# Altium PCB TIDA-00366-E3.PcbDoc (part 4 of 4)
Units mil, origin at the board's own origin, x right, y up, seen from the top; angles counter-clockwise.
Board outline 6298.95 x 6141.73 mil, 4 copper layers (Top Layer, GND, PWR, Bottom Layer), stack 79.834 mil thick; 362 components, 168 nets, 919 pads, 271 vias.
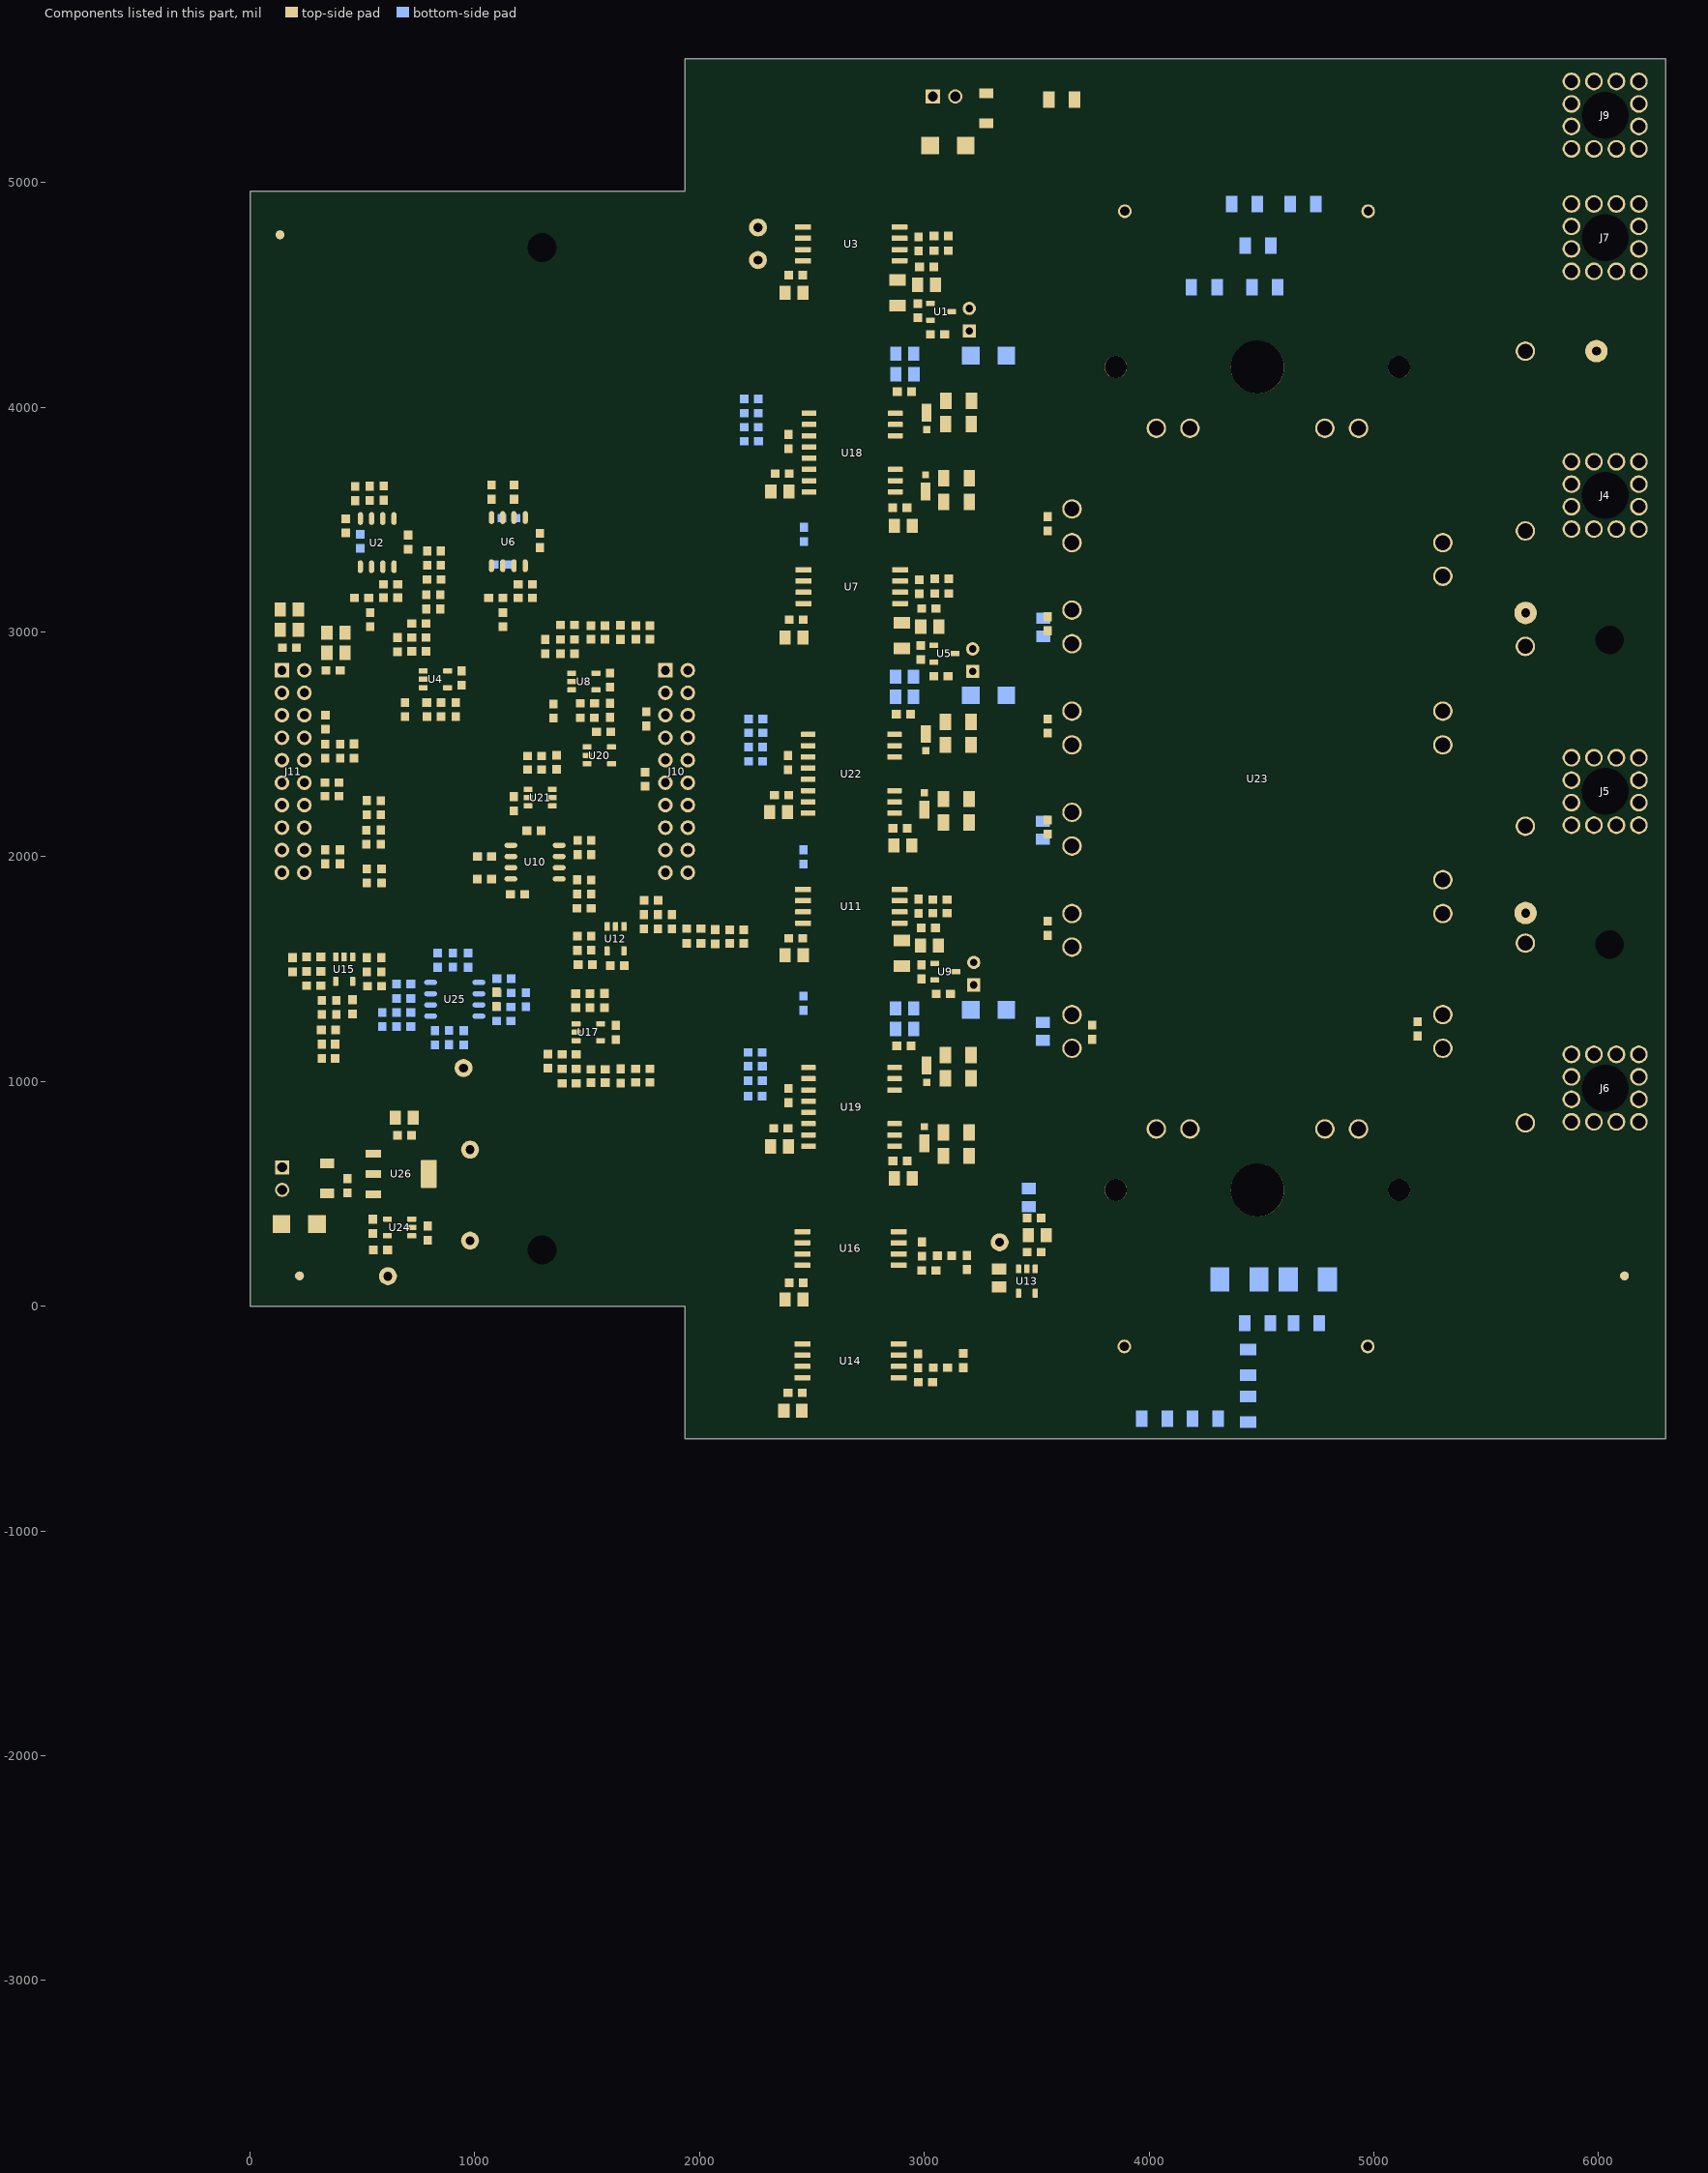
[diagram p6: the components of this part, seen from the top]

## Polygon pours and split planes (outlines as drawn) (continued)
U_TOP_REF on Bottom Layer "Top Layer-No Net 1" (solid, remove dead copper, pour order 81): 5754.73,4304.45 5768.22,4290.96 5768.22,4259.45 5768.22,4202.94 5754.73,4189.45 5564.73,4189.45 5479.73,4104.45 5371.5,3996.21 5371.5,3594.45 5371.5,3201.21 5359.73,3189.45 5254.73,3189.45 5249.73,3194.45 5249.73,4029.45 5519.73,4299.45 5524.73,4304.45 5754.73,4304.45
VDC+ on Bottom Layer "Top Layer-No Net 1" (solid, remove dead copper, pour order 86): 5884.73,4949.45 4719.73,4949.45 4709.73,4939.45 4709.73,-210.55 4749.73,-250.55 5024.73,-250.55 5044.73,-230.55 5044.73,-105.55 4994.73,-55.55 4994.73,4499.45 5054.73,4559.45 5924.73,4559.45 6229.73,4559.45 6244.73,4574.45 6244.73,4934.45 6229.73,4949.45
VDC- on Bottom Layer "Top Layer-No Net 1" (solid, remove dead copper, pour order 92): 6244.73,5474.45 6244.73,5124.45 6224.73,5104.45 4269.73,5104.45 4224.73,5059.45 4224.73,-225.55 4199.73,-250.55 3829.73,-250.55 3814.73,-235.55 3814.73,-125.55 3934.73,-5.55 3934.73,4484.45 3764.73,4654.45 3764.73,5464.45 3789.73,5489.45 3794.73,5494.45 3869.73,5494.45 6224.73,5494.45 6244.73,5474.45
VCC_U on PWR "PWR-No Net" (solid, remove dead copper, pour order 129): 3246.73,4194.45 3246.73,3865.45 3239.73,3858.45 2825.73,3858.45 2821.73,3862.45 2820.73,3863.45 2820.73,3875.45 2820.73,4830.45 2839.73,4849.45 3226.73,4849.45 3242.73,4833.45 3246.73,4829.45 3246.73,4196.45
VCC_V on PWR "PWR-No Net" (solid, remove dead copper, pour order 131): 3246.73,2765.45 3246.73,2431.45 3241.73,2426.45 3238.73,2429.45 2862.73,2429.45 2827.32,2429.45 2819.73,2437.04 2819.73,3311.5 2830.69,3322.45 3224.73,3322.45 3237.73,3309.45 3246.73,3300.45 3246.73,2766.45
VCC_W on PWR "PWR-No Net" (solid, remove dead copper, pour order 133): 3247.73,1282.45 3247.73,953.45 3241.73,947.45 2823.86,947.45 2819.86,951.45 2819.86,1892.1 2824.34,1896.58 3225.61,1896.58 3242.73,1879.45 3247.73,1874.45 3247.73,1289.45
+16V_GPS on PWR "PWR-No Net" (solid, remove dead copper, pour order 134): 3324.73,4266.45 3324.73,3745.45 3313.73,3734.45 2825.65,3734.45 2820.73,3729.54 2820.73,3443.45 2831.73,3432.45 3284.73,3432.45 3322.73,3394.45 3324.73,3392.45 3324.73,2759.45 3324.73,2319.45 3313.73,2308.45 2826.65,2308.45 2819.73,2301.54 2819.73,2020.45 2830.73,2009.45 3300.73,2009.45 3316.73,1993.45 3324.73,1985.45 3324.73,1278.45 3324.73,868.45 3289.73,833.45 3282.73,826.45 2855.73,826.45 2823.86,826.45 2819.86,822.45 2819.86,540.86 2831.86,528.86 3547.15,528.86 3561.15,528.86 3575.73,543.45 3575.73,5488.45 3569.73,5494.45 3334.73,5494.45 3324.73,5484.45
W_PHASE on PWR "Top Layer-No Net 1" (solid, remove dead copper, pour order 100): 6214.73,1179.45 5797.73,1179.45 5787.73,1169.45 5787.73,879.45 5779.73,871.45 5595.73,871.45 5579.25,854.96 5579.25,769.94 5592.73,756.45 6211.73,756.45 6234.73,779.45 6234.73,1160.45 6214.73,1180.45
W_TOP_REF on PWR "Top Layer-No Net 1" (solid, remove dead copper, pour order 71): 5239.73,1944.45 5239.73,1714.45 5259.73,1694.45 5569.73,1694.45 5579.73,1684.45 5579.73,1584.45 5589.73,1574.45 5753.22,1574.45 5768.22,1589.45 5768.22,1740.96 5749.73,1759.45 5724.73,1784.45 5384.73,1784.45 5371.5,1797.69 5371.5,1799.45 5371.5,1937.69 5359.73,1949.45 5244.73,1949.45 5239.73,1944.45
V_PHASE on PWR "Top Layer-No Net 1" (solid, remove dead copper, pour order 91): 6214.73,2499.45 5797.73,2499.45 5787.73,2489.45 5787.73,2199.45 5779.73,2191.45 5595.73,2191.45 5579.25,2174.96 5579.25,2089.94 5592.73,2076.45 6211.73,2076.45 6234.73,2099.45 6234.73,2480.45 6214.73,2500.45
V_TOP_REF on PWR "Top Layer-No Net 1" (solid, remove dead copper, pour order 76): 5254.73,2689.45 5254.73,2459.45 5264.73,2449.45 5361.5,2449.45 5371.5,2459.45 5371.5,2866.21 5389.73,2884.45 5759.73,2884.45 5764.73,2889.45 5764.73,2984.45 5749.73,2999.45 5269.73,2999.45 5254.73,2984.45
U_PHASE on PWR "Top Layer-No Net 1" (solid, remove dead copper, pour order 96): 6214.73,3811.45 5797.73,3811.45 5787.73,3801.45 5787.73,3511.45 5779.73,3503.45 5595.73,3503.45 5579.25,3486.96 5579.25,3401.94 5592.73,3388.45 6211.73,3388.45 6234.73,3411.45 6234.73,3792.45 6214.73,3812.45
U_TOP_REF on PWR "Top Layer-No Net 1" (solid, remove dead copper, pour order 80): 5754.73,4304.45 5768.22,4290.96 5768.22,4259.45 5768.22,4202.94 5754.73,4189.45 5564.73,4189.45 5479.73,4104.45 5371.5,3996.21 5371.5,3594.45 5371.5,3201.21 5359.73,3189.45 5254.73,3189.45 5249.73,3194.45 5249.73,4029.45 5519.73,4299.45 5524.73,4304.45 5754.73,4304.45
VDC+ on PWR "Top Layer-No Net 1" (solid, remove dead copper, pour order 85): 5884.73,4949.45 4719.73,4949.45 4709.73,4939.45 4709.73,-210.55 4749.73,-250.55 5024.73,-250.55 5044.73,-230.55 5044.73,-105.55 4994.73,-55.55 4994.73,4499.45 5054.73,4559.45 5924.73,4559.45 6229.73,4559.45 6244.73,4574.45 6244.73,4934.45 6229.73,4949.45
VDC- on PWR "Top Layer-No Net 1" (solid, remove dead copper, pour order 90): 6244.73,5474.45 6244.73,5124.45 6224.73,5104.45 4269.73,5104.45 4224.73,5059.45 4224.73,-225.55 4199.73,-250.55 3829.73,-250.55 3814.73,-235.55 3814.73,-125.55 3934.73,-5.55 3934.73,4484.45 3764.73,4654.45 3764.73,5464.45 3789.73,5489.45 3794.73,5494.45 3869.73,5494.45 6224.73,5494.45 6244.73,5474.45
5V_VDC on PWR "Top Layer-No Net 1" (solid, remove dead copper, pour order 106): 2824.73,424.45 2824.73,-530.55 2844.73,-550.55 3544.73,-550.55 3559.73,-535.55 3559.73,404.45 3539.73,424.45 3527.47,436.72 2837,436.72
VCCI on PWR "Top Layer-No Net 1" (solid, remove dead copper, pour order 126): 2480,5495 1990,5495 1980,5485 1980,4945 1950,4915 45,4915 30,4900 30,55 45,40 1960,40 1980,20 1980,-540 1990,-550 2515,-550 2520,-545 2520,5490 2515,5495
GND1 on GND "Top Layer-No Net 1" (solid, remove dead copper, pour order 136): 3324.73,5484.45 3324.73,533.45 3329.73,528.45 3560.73,528.45 3575.73,543.45 3575.73,5488.45 3569.73,5494.45 3334.73,5494.45
W_TOP_REF on GND "PWR-No Net" (solid, remove dead copper, pour order 132): 3247.73,1282.45 3247.73,953.45 3241.73,947.45 2823.86,947.45 2819.86,951.45 2819.86,1892.1 2824.34,1896.58 3225.61,1896.58 3242.73,1879.45 3247.73,1874.45 3247.73,1289.45
V_TOP_REF on GND "PWR-No Net" (solid, remove dead copper, pour order 130): 3246.73,2765.45 3246.73,2431.45 3241.73,2426.45 3238.73,2429.45 2862.73,2429.45 2827.32,2429.45 2819.73,2437.04 2819.73,3311.5 2830.69,3322.45 3224.73,3322.45 3237.73,3309.45 3246.73,3300.45 3246.73,2766.45
U_TOP_REF on GND "PWR-No Net" (solid, remove dead copper, pour order 128): 3246.73,4194.45 3246.73,3865.45 3239.73,3858.45 2825.73,3858.45 2821.73,3862.45 2820.73,3863.45 2820.73,3875.45 2820.73,4830.45 2839.73,4849.45 3226.73,4849.45 3242.73,4833.45 3246.73,4829.45 3246.73,4196.45
VDC- on GND "Top Layer-No Net 1" (solid, remove dead copper, pour order 105): 2824.73,424.45 2824.73,-530.55 2844.73,-550.55 3544.73,-550.55 3559.73,-535.55 3559.73,404.45 3539.73,424.45 3527.47,436.72 2837,436.72
W_PHASE on GND "Top Layer-No Net 1" (solid, remove dead copper, pour order 99): 6214.73,1179.45 5797.73,1179.45 5787.73,1169.45 5787.73,879.45 5779.73,871.45 5595.73,871.45 5579.25,854.96 5579.25,769.94 5592.73,756.45 6211.73,756.45 6234.73,779.45 6234.73,1160.45 6214.73,1180.45
W_TOP_REF on GND "Top Layer-No Net 1" (solid, remove dead copper, pour order 70): 5239.73,1944.45 5239.73,1714.45 5259.73,1694.45 5569.73,1694.45 5579.73,1684.45 5579.73,1584.45 5589.73,1574.45 5753.22,1574.45 5768.22,1589.45 5768.22,1740.96 5749.73,1759.45 5724.73,1784.45 5384.73,1784.45 5371.5,1797.69 5371.5,1799.45 5371.5,1937.69 5359.73,1949.45 5244.73,1949.45 5239.73,1944.45
V_PHASE on GND "Top Layer-No Net 1" (solid, remove dead copper, pour order 89): 6214.73,2499.45 5797.73,2499.45 5787.73,2489.45 5787.73,2199.45 5779.73,2191.45 5595.73,2191.45 5579.25,2174.96 5579.25,2089.94 5592.73,2076.45 6211.73,2076.45 6234.73,2099.45 6234.73,2480.45 6214.73,2500.45
V_TOP_REF on GND "Top Layer-No Net 1" (solid, remove dead copper, pour order 75): 5254.73,2689.45 5254.73,2459.45 5264.73,2449.45 5361.5,2449.45 5371.5,2459.45 5371.5,2866.21 5389.73,2884.45 5759.73,2884.45 5764.73,2889.45 5764.73,2984.45 5749.73,2999.45 5269.73,2999.45 5254.73,2984.45
U_PHASE on GND "Top Layer-No Net 1" (solid, remove dead copper, pour order 95): 6214.73,3811.45 5797.73,3811.45 5787.73,3801.45 5787.73,3511.45 5779.73,3503.45 5595.73,3503.45 5579.25,3486.96 5579.25,3401.94 5592.73,3388.45 6211.73,3388.45 6234.73,3411.45 6234.73,3792.45 6214.73,3812.45
U_TOP_REF on GND "Top Layer-No Net 1" (solid, remove dead copper, pour order 79): 5754.73,4304.45 5768.22,4290.96 5768.22,4259.45 5768.22,4202.94 5754.73,4189.45 5564.73,4189.45 5479.73,4104.45 5371.5,3996.21 5371.5,3594.45 5371.5,3201.21 5359.73,3189.45 5254.73,3189.45 5249.73,3194.45 5249.73,4029.45 5519.73,4299.45 5524.73,4304.45 5754.73,4304.45
VDC+ on GND "Top Layer-No Net 1" (solid, remove dead copper, pour order 84): 5884.73,4949.45 4719.73,4949.45 4709.73,4939.45 4709.73,-210.55 4749.73,-250.55 5024.73,-250.55 5044.73,-230.55 5044.73,-105.55 4994.73,-55.55 4994.73,4499.45 5054.73,4559.45 5924.73,4559.45 6229.73,4559.45 6244.73,4574.45 6244.73,4934.45 6229.73,4949.45
VDC- on GND "Top Layer-No Net 1" (solid, remove dead copper, pour order 88): 6244.73,5474.45 6244.73,5124.45 6224.73,5104.45 4269.73,5104.45 4224.73,5059.45 4224.73,-225.55 4199.73,-250.55 3829.73,-250.55 3814.73,-235.55 3814.73,-125.55 3934.73,-5.55 3934.73,4484.45 3764.73,4654.45 3764.73,5464.45 3789.73,5489.45 3794.73,5494.45 3869.73,5494.45 6224.73,5494.45 6244.73,5474.45
GND on GND "Top Layer-No Net 1" (solid, remove dead copper, pour order 125): 2480,5495 1990,5495 1980,5485 1980,4945 1950,4915 45,4915 30,4900 30,55 45,40 1960,40 1980,20 1980,-540 1990,-550 2515,-550 2520,-545 2520,5490 2515,5495

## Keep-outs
Keep-Out Layer:
  text ".Layer_Name" at 111.73,-3325.04 h60

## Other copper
Top Layer:
  text ".layer_Name" at 126.73,-3314.55 h60
GND:
  text "GND" at 194.73,-3310.55 h60
PWR:
  text "PWR" at 204.73,-3310.55 h60
Bottom Layer:
  text ".Layer_Name" at 185.73,-3324.55 h60
Multi-Layer:
  pour cut-out: 2817.3,-545 2522.7,-545 2522.7,5500 2817.3,5500

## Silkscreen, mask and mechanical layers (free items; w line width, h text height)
Top Overlay:
  circle w10: c5989.73,4249.45 r70.51
  circle w10: c5674.73,3084.45 r70.51
  circle w10: c5674.73,1749.45 r70.51
  lines w6: 257.73,1311.4 281.73,1311.4 ; 276.73,1593.4 276.73,1638.4 ; 449.73,1629.45 454.73,1624.45 454.73,1594.45 ; 455.73,2867.45 463.73,2859.45 474.73,2859.45 ; 544.73,2479.45 504.73,2479.45 ; 545.93,2278.43 545.93,2290.64 553.74,2298.45 ; 550.73,803.45 567.73,803.45 583.53,787.65 626.75,787.65 ; 614.73,3074.45 624.73,3084.45 624.73,3109.45 ; 729,2726.02 729,2713 746,2696 ; 814.73,2549.45 814.73,2589.45 ; 1238.06,2935.12 1276.06,2935.12 ; 1354.73,2873.27 1354.73,2864.45 1474.06,2864.45 1474.06,2872.62 ; 1354.73,3069.45 1354.73,3094.45 1394.73,3134.45 1394.73,3249.45 1504.73,3249.45 1504.73,3119.45 1479.73,3094.45 1479.73,3069.45 ; 1379.73,1189.45 1419.73,1189.45 ; 1419.73,1609.45 1389.73,1609.45 ; 1424.73,3069.45 1424.73,3099.45 ; 1429.73,914.45 1429.73,944.45 ; 1483.5,1926.93 1483.5,1939.45 1492.96,1948.91 ; 1639.73,2784.45 1664.73,2784.45 ; 1659.73,1219.45 1689.73,1219.45 ; 2950.73,125.45 2953.02,125.45 2959.75,132.18 ; 2955.73,333.45 2955.73,321.17 2962.47,314.43 ; 3069.72,4597.18 3119.47,4597.18 3127.73,4605.45 ; 3077.72,1656.18 3120.47,1656.18 3134.73,1670.45 ; 3079.72,3077.18 3130.47,3077.18 3136.73,3083.45 ; 3102.29,4483.5 3133.79,4515 3140,4515 ; 3116.29,2962.5 3124.5,2962.5 3152,2990 ; 3120.29,1547.5 3137.5,1547.5 3150,1560 3150,1595 3154,1599 3160,1605 ; 3131.72,-300.82 3131.72,-312.53 ; 3139.73,179.45 3149.72,189.43 3149.72,197.18 ; 276.73,1638.4 284.73,1630.4 268.73,1630.4 276.73,1638.4 ; 281.73,1311.4 274.73,1318.4 274.73,1301.4 281.73,1308.4 281.73,1311.4 ; 504.73,2479.45 514.73,2469.45 514.73,2489.45 504.73,2479.45 ; 814.73,2589.45 824.73,2579.45 804.73,2579.45 814.73,2589.45 ; 1389.73,1609.45 1399.73,1599.45 1399.73,1619.45 1389.73,1609.45 ; 1424.73,3099.45 1434.73,3089.45 1414.73,3089.45 1424.73,3099.45 ; 1429.73,944.45 1439.73,934.45 1419.73,934.45 1429.73,944.45 ; 3131.72,-312.53 3131.73,-312.55
  lines w10: -757.27,-3396.72 5842.73,-3396.72 ; -757.27,-3193.38 5844.73,-3193.38 ; -757.27,-2990.05 -757.27,-3600.05 3247.73,-3600.05 5844.73,-3600.05 ; -756.77,-3600.05 -756.77,-2990.05 5844.73,-2990.05 ; 1725.73,-3598.55 1725.73,-2988.55 ; 3934.73,-3194.88 3934.73,-2991.55 ; 4608.73,-3600.38 4608.73,-3397.55 ; 5844.23,-3600.05 5844.23,-2990.05
  text "GD_Supply" at 2530,5460 h50
  text "GND" at 3225,5460 h50
  text "VDC-" at 5780,5235 h50 r90
  text "840V DC" at 5120,5008 h100
  text "VDC+" at 5795,4640 h50 r90
  text "DANGER HIGH VOLTAGE" at 5073,4490 h50
  text "U_PHASE" at 5865,3830 h50
  text "DANGER HIGH VOLTAGE" at 4612,3572 h50
  text "V_PHASE" at 5855,2515 h50
  text "DANGER HIGH VOLTAGE" at 4802,1960 h50
  text "W_PHASE" at 5870,1200 h50
  text "GND" at 85,700 h50 r90
  text "DANGER HIGH VOLTAGE" at 4874,607 h50
  text "5V_VIN" at 75,155 h50 r90
  text ".layer_Name" at 152.73,-3312.55 h60
Bottom Overlay:
  lines w6: 699.73,1479.45 699.73,1519.45 ; 1026,1474 1026,1492 ; 1132.76,1494.45 1132.76,1539.45 ; 699.73,1519.45 709.73,1509.45 689.73,1509.45 699.73,1519.45 ; 1026,1492 1026,1491 1031,1486 1020,1486 1026,1492 ; 1132.76,1539.45 1133.76,1539.45 1140.76,1532.45 1125.76,1532.45 1132.76,1539.45
  text ".Layer_Name" at 111.73,-3325.04 h60
Top Paste:
  text ".Layer_Name" at 99.73,-3328.04 h60
Bottom Paste:
  text ".Layer_Name" at 99.73,-3328.04 h60
Top Solder:
  text ".Layer_Name" at 127.73,-3335.55 h60
Bottom Solder:
  text ".Layer_Name" at 174.73,-3331.55 h60
M1 Board Outline:
  the board outline again, w20
  text "'.Layer_Name'" at 127,-3320 h60
M2 Board Dimensions:
  rectangle: -645.5,-2646 -520.5,-2521
  rectangle: -520.5,-2771 -145.5,-2646
  lines w7: -645.5,-2646 354.5,-2646 ; -520.5,-2771 -520.5,-2521 ; -395.5,-2771 -395.5,-2521 ; -145.5,-2771 -145.5,-2521 ; 104.5,-2771 104.5,-2521 ; -645.5,-2771 354.5,-2771 354.5,-2521 -645.5,-2521 -645.5,-2771
  lines w10: -645.5,-2836 -645.5,-2816 ; -585.5,-2846 -645.5,-2826 ; -585.5,-2806 -645.5,-2826 ; -421.42,-2826 -645.5,-2826 ; 130.42,-2826 354.5,-2826 ; 294.5,-2846 354.5,-2826 ; 294.5,-2806 354.5,-2826 ; 354.5,-2836 354.5,-2816
  text "1000 (mil)" at -411.42,-2861.99 h60
M3 3D STEP Top:
  text ".Layer_Name" at 111.73,-3325.04 h60
M4 3D STEP Bottom:
  text ".Layer_Name" at 111.73,-3325.04 h60
M5 Assembly Top:
  circle w10: c3494.73,189.84 r11.18
  circle w10: c1424.73,1254.45 r11.18
  circle w10: c3084.73,1524.45 r8
  circle w10: c3079.73,2939.45 r8
  circle w10: c3064.73,4459.45 r8
  circle w10: c455,1575 r10.63
  circle w10: c1409.73,2816.52 r8.16
  circle w10: c749.73,2826.85 r8.16
  circle w10: c1663.36,1714.45 r8.16
  circle w10: c513.73,681.45 r8.16
  circle w10: c3199.73,4339.45 r8
  circle w10: c3214.73,2819.45 r8
  circle w10: c3219.73,1429.45 r8
  circle w10: c5989.73,4249.45 r70.51
  circle w10: c5674.73,3084.45 r70.51
  circle w10: c5674.73,1749.45 r70.51
  lines w6: -757.27,-3192.55 5846.73,-3192.55 ; -755.77,-3396.55 5848.73,-3396.55 ; 1725.73,-3598.05 1725.73,-2990.55 ; 2262.73,-3192.55 2262.73,-2990.05 ; 2974.73,-3189.88 2974.73,-2989.55 ; 3373.73,-3597.55 3373.73,-2990.05 ; 3934.73,-3189.55 3934.73,-2990.55 ; 5846.23,-3596.05 5846.23,-2990.05 -756.27,-2990.05 -756.27,-3598.55 5848.73,-3598.55 ; 6976.23,-2990.05 6978.73,-2992.55
  text "TP10" at 5949.73,4339.45 h25
  text "TP8" at 5639.73,3074.45 h25
  text "TP9" at 5629.73,1739.45 h25
  text "COMPONENTS MARKED 'DNP' SHOULD NOT BE POPULATED." at 688.23,-2785.05 h25
  text "ASSEMBLY VARIANT:" at 687.73,-2900.55 h25
  text ".VariantName" at 1723.73,-2900.55 h25
  text "ALL ARTWORK VIEWED FROM TOP SIDE" at -693.77,-3122.22 h25
  text "BOARD #:" at 1782.73,-3122.22 h25
  text ".PRJ_Number" at 2328.23,-3122.22 h25
  text "REV:" at 3172.73,-3122.22 h25
  text ".PCB_Rev" at 3464.23,-3122.22 h25
  text "SVN REV:" at 4010.73,-3122.22 h25
  text ".VersionControl_RevNumber" at 4516.73,-3122.22 h25
  text ".layer_Name" at 69.73,-3304.55 h25
  text ".PRJ_Number" at 2173.23,-3307.22 h25
  text "LAYER NAME =" at -700.27,-3311.55 h25
  text "TID #:" at 1797.73,-3312.22 h25
  text ".plot_File_Name" at -702.27,-3500.55 h25
  text "GENERATED    :" at 1784.73,-3530.88 h25
  text ".Print_Date" at 2654.23,-3530.88 h25
  text ".Print_Time" at 3383.23,-3530.88 h25
  text "TEXAS INSTRUMENTS" at 4647.73,-3530.88 h25
M6 Assembly Bottom:
  lines w6: -757.77,-3193.88 5844.23,-3193.88 ; -755.77,-3397.22 5844.23,-3397.22 ; 1380.73,-3193.38 1380.73,-2990.05 ; 1839.23,-3600.55 -757.77,-3600.55 -757.77,-2990.55 5843.73,-2990.55 ; 1839.23,-3600.05 5844.23,-3600.05 ; 2262.73,-3194.88 2262.73,-2991.55 ; 3373.73,-3600.55 3373.73,-2990.55 ; 4269.23,-3600.05 5844.73,-3600.05 ; 5844.23,-3600.55 5844.23,-2990.55 5844.23,-3600.55
  text "COMPONENTS MARKED 'DNP' SHOULD NOT BE POPULATED." at 5636.73,-2784.55 h25
  text ".VariantName" at 4592.73,-2900.55 h25
  text "ASSEMBLY VARIANT:" at 5631.73,-2900.55 h25
  text "SVN REV:" at 1076.23,-3122.72 h25
  text ".PCB_Rev" at 1622.73,-3122.72 h25
  text "REV:" at 1914.23,-3122.72 h25
  text ".PRJ_Number" at 2758.73,-3122.72 h25
  text "BOARD #:" at 3304.23,-3122.72 h25
  text "PCB VIEWED FROM BOTTOM SIDE" at 5780.73,-3122.72 h25
  text "Not in versioncontrol" at 735,-3125 h25
  text ".PRJ_Number" at 2921.77,-3303.22 h25
  text "LAYER NAME =" at 5775.73,-3307.55 h25
  text "TID #:" at 3297.27,-3308.22 h25
  text ".Layer_Name" at 5002.73,-3314.55 h25
  text "IGNORE ->" at 2082.58,-3325.04 h25
  text ".Print_Time" at 1703.73,-3531.38 h25
  text ".Print_Date" at 2432.73,-3531.38 h25
  text "GENERATED    :" at 3302.23,-3531.38 h25
  text ".plot_File_Name" at 4975.23,-3531.38 h25
  text "PLOT NAME =" at 5780.73,-3531.38 h25
M9 Title Sheet:
  drawing of 57 lines, arcs and shapes, not listed
  text "4" at 7771.24,10334.95 h70
  text "5" at 10270.23,10334.95 h70
  text "1" at 319.73,10329.45 h70
  text "2" at 2724.73,10324.45 h70
  text "3" at 5249.73,10324.45 h70
  text "6" at 12639.73,10324.45 h70
  text "A" at -881.77,4426.95 h70
  text "A" at 13918.23,4426.95 h70
  text "B" at -881.77,2046.95 h70
  text "B" at 13918.23,2046.95 h70
  text "C" at -881.77,-328.05 h70
  text "C" at 13918.23,-328.05 h70
  text "PROJECT TITLE:" at 10878.23,-2189.05 h45
  text ".PRJ_Title" at 11089,-2310 h70
  text "DESIGNED FOR:" at 10878.23,-2490.05 h45
  text ".PRJ_Customer" at 10928.23,-2630.05 h70
  text "D" at -881.77,-2698.05 h70
  text "D" at 13918.23,-2698.05 h70
  text "FILE NAME:" at 10878.23,-2790.05 h45
  text ".PCB_File_Name_No_Path" at 11209.73,-2915.55 h70
  text "Texas Instruments (TI) and/or its licensors do not warrant the accuracy or completeness of this specification" at 5908.73,-3071.89 h45
  text "ENGINEER:" at 10878.23,-3080.05 h45
  text "LAYOUT BY:" at 12383.23,-3080.05 h45
  text "or any information contained therein. TI and/or its licensors do not warrant that this design will meet" at 5863.75,-3184.55 h45
  text ".PRJ_Engineer" at 11127.23,-3209.55 h40
  text ".PCB_Layout" at 12632.73,-3209.55 h40
  text "the specifications, will be suitable for your application or fit for any particular purpose, or will operate in" at 5863.75,-3297.22 h45
  text "ALTIUM DESIGNER VERSION:" at 12383.23,-3390.05 h45
  text "an implementation. TI and/or its licensors do not warrant that the design is production worthy. You should" at 5863.75,-3409.88 h45
  text "completely validate and test your design implementation to confirm the system functionality for your application." at 5908.73,-3522.55 h45
  text ".print_Scale" at 10928.23,-3523.38 h70
  text ".Application_BuildNumber" at 12433.73,-3523.38 h70
  text "2" at 2770.23,-3730.05 h70
  text "3" at 5259.58,-3730.05 h70
  text "4" at 7766.24,-3730.05 h70
  text "5" at 10265.23,-3730.05 h70
  text "6" at 12770.23,-3730.05 h70
M10 Fab Notes:
  drawing of 228 lines, arcs and shapes, not listed
  text "DESIGN INFORMATION" at 11915.75,4343.45 h60
  text "(REFER ALSO ARRAY/PANEL PROFILING INFORMATION)" at 11554.19,4181.74 h60
  text "BOARD SIZE" at 10868.19,4177.45 h60
  text "160MM" at 11330.51,4049.63 h60
  text "X" at 11836.19,4049.63 h60
  text "156MM" at 12067.51,4049.63 h60
  text "Number of Layers :" at 11271.19,3852.45 h60
  text "4" at 12366,3842.45 h60
  text "MIN. TRACK WIDTH:" at 11271.19,3713.45 h60
  text "12" at 12367.43,3713.45 h60
  text "MIL" at 12522.19,3713.45 h60
  text "8" at 12369.73,3589.45 h60
  text "MIN. CLEARANCE:" at 11271.19,3581.45 h60
  text "MIL" at 12522.19,3581.45 h60
  text "16" at 12345,3465 h60
  text "MIN. VIA DRILL SIZE:" at 11271.19,3449.45 h60
  text "MIL" at 12522.19,3449.45 h60
  text "8 MIL" at 11966.19,3307.74 h60
  text "MINIMUM ANNULAR RING" at 10941.96,3303.46 h60
  text "EXTERNAL" at 12674.19,3303.46 h60
  text "PER" at 11141.96,3185.45 h60
  text "IPC-D-275 CLASS 2 LEVEL C" at 11361.96,3185.45 h60
  text "MIL, HOLES" at 12850.19,3073.16 h60
  text "+/-" at 12457.73,3072.45 h60
  text "+/-" at 13311.73,3072.45 h60
  text "REGISTRATION TOLERANCES:" at 10941.96,3067.45 h60
  text "METAL" at 12141.73,3067.45 h60
  text "5" at 12717.93,3067.45 h60
  text "3" at 13550.93,3067.45 h60
  text "MIL" at 13667.19,3067.45 h60
  text "MATERIAL:" at 10867.19,2857.99 h60
  text "FR-4 High Tg" at 11853.64,2717.66 h60
  text "FR-408" at 11288.19,2709.09 h60
  text "X" at 11694.73,2709.45 h60
  text "OTHER" at 12776.19,2709.09 h60
  text "63 MIL (1.6mm) +/-10%" at 11608.3,2546.37 h60
  text "THICKNESS:" at 10941.96,2542.09 h60
  text "X" at 11480.13,2542.09 h60
  text "OTHER" at 12893.19,2542.09 h60
  text "TOLERANCE:" at 10941.96,2384.09 h60
  text "X" at 11781.27,2384.09 h60
  text "ANSI IPC-6012 TYPE 3 CLASS 2" at 11968.21,2384.09 h60
  text "OTHER +/-" at 11968.19,2228.09 h60
  text "BOW & TWIST:" at 10941.96,2071.09 h60
  text "X" at 11781.27,2071.09 h60
  text "ANSI IPC-6012 TYPE 3 CLASS 2" at 11968.21,2071.09 h60
  text "OTHER +/-" at 11968.19,1912.58 h60
  text "COPPER THICKNESS (FINISHED):" at 10867.19,1777.09 h60
  text "1.4MIL (1oz)" at 11747.19,1624.37 h60
  text "2MIL (1.4oz)" at 12514.19,1624.37 h60
  text "2.8MIL (2oz)" at 13241.19,1624.37 h60
  text "OUTER:" at 11224.19,1620.09 h60
  text "X" at 11611.73,1616.45 h60
  text "X" at 11618.73,1474.45 h60
  text "1.4MIL (1oz)" at 11747.19,1467.37 h60
  text "2.8MIL (2oz)" at 12514.19,1467.37 h60
  text "N/A" at 13240.73,1467.74 h60
  text "INNER SIGNAL:" at 10935.11,1463.09 h60
  text "DRILLING:" at 10867.19,1324.09 h60
  text "REFERENCE:" at 10941.96,1207.09 h60
  text "X" at 11590.19,1207.09 h60
  text "AS SHOWN" at 11777.19,1207.09 h60
  text "X" at 12491.19,1207.09 h60
  text "NC_DRILL FILES" at 12628.19,1207.09 h60
  text "PTH MIN COPPER THICKNESS:" at 10941.96,1049.09 h60
  text "X" at 12292.19,1049.09 h60
  text "1MIL" at 12429.19,1049.09 h60
  text "OTHER" at 12926.19,1049.09 h60
  text "BOARD FINISH:" at 10867.19,890.09 h60
  text "SILKSCREEN:" at 11022.41,772.09 h60
  text "X" at 11971.19,772.09 h60
  text "TOP" at 12097.19,772.09 h60
  text "X" at 12481.19,772.09 h60
  text "BOTTOM" at 12608.19,772.09 h60
  text "SILKSCREEN COLOR:" at 11022.41,605.09 h60
  text "X" at 11970.15,605.09 h60
  text "WHITE" at 12097.19,605.09 h60
  text "OTHER" at 12608.19,605.09 h60
  text "SOLDER RESIST COLOR:" at 11022.41,435.09 h60
  text "X" at 11590.16,275.89 h60
  text "GREEN" at 11717.19,275.89 h60
  text "BLUE" at 12308.19,275.89 h60
  text "OTHER" at 12846.19,275.89 h60
  text "IMMERSION GOLD (ENIG)" at 11928.19,87.37 h60
  text "ENEPIG" at 13265.73,84.09 h60
  text "SURFACE FINISH:" at 10867.19,83.09 h60
  text "X" at 11741.25,83.09 h60
  text "IMM. TIN/SILVER OR EQUIV" at 11196.73,-73.91 h60
  text "OTHER" at 12628.19,-73.91 h60
  text "ARRAY/PANEL:" at 10867.19,-252.91 h60
  text "CUT AND TRIM PER MECH LAYER 1" at 11928.19,-257.2 h60
  text "N.C. ROUTE" at 11928.19,-408.91 h60
  text "X" at 12607.19,-408.91 h60
  text "V. SCORE" at 12794.19,-408.91 h60
  text "CERTIFICATION:" at 10867.19,-545.91 h60
  text "MATERIALS AND WORKMANSHIP FOR ALL PCBS" at 11592.19,-545.91 h60
  text "TO MEET OR EXCEED THE REQUIREMENTS OF:" at 11592.19,-643.91 h60
  text "X" at 11218.7,-780.41 h60
  text "ANSI IPC-A-600F CLASS ->" at 11357.7,-780.41 h60
  text "X" at 12996.75,-780.41 h60
  text "2" at 13115.7,-780.41 h60
  text "1" at 12800.7,-781.91 h60
  text "3" at 13469.7,-781.91 h60
  text "X" at 11220.75,-939.91 h60
  text "UL 94V-0" at 11357.7,-939.91 h60
  text "X" at 12032.75,-939.91 h60
  text "RoHS" at 12169.7,-939.91 h60
  text "OTHER" at 12814.1,-939.91 h60
  text "PER ORDER" at 13211.16,-939.91 h60
  text "VIA TENTING:" at 12084.73,-1073.55 h60
  text "X" at 13164.73,-1075.55 h60
  text "ADDITIONAL REQUIREMENTS:" at 10867.19,-1080.91 h60
  text "YES" at 12634.4,-1082.63 h60
  text "NO" at 12999.21,-1087.86 h60
  text "MICROSECTION:" at 10941.96,-1195.91 h60
  text "YES" at 11847.7,-1195.91 h60
  text "IMPEDANCE CONTROL:" at 12106.73,-1202.55 h60
  text "YES" at 13090.73,-1203.55 h60
  text "X" at 13632.73,-1210.55 h60
  text "NO" at 13466.21,-1220.86 h60
  text "REQUIRED" at 12709.19,-1352.05 h60
  text "BARE BOARD ELEC. TEST:" at 10941.96,-1354.91 h60
  text "NONE" at 12247.7,-1354.91 h60
  text "X" at 12582.19,-1354.91 h60
  text "PER ORDER" at 13301.19,-1354.91 h60
  text "MANUFACTURER'S UL:" at 10941.96,-1511.91 h60
  text "RAIL" at 12107.7,-1516.2 h60
  text "METAL" at 12599.51,-1516.2 h60
  text "X" at 12974.73,-1516.55 h60
  text "SILK" at 13111.19,-1516.2 h60
M11 Gerber Information:
  lines w10: -758.27,-3600.05 3246.73,-3600.05 ; -757.27,-3600.05 -757.27,-2990.05 ; -757.27,-3396.72 5842.73,-3396.72 ; -757.27,-3193.38 5844.73,-3193.38 ; -756.77,-3600.05 -756.77,-2990.05 5844.73,-2990.05 5844.73,-3600.05 3247.73,-3600.05 ; 1725.73,-3598.55 1725.73,-2988.55 ; 4608.73,-3600.38 4608.73,-3397.55 ; 3934.73,-3194.88 3934.73,-2991.55 3934.73,-3194.88
  text "BOARD #:" at 1782.73,-3122.22 h60
  text ".PRJ_Number" at 2328.23,-3122.22 h60
  text "REV:" at 3172.73,-3122.22 h60
  text ".PCB_Rev" at 3464.23,-3122.22 h60
  text "SVN REV:" at 4010.73,-3122.22 h60
  text ".VersionControl_RevNumber" at 4516.73,-3122.22 h60
  text "ALL ARTWORK VIEWED FROM TOP SIDE" at -694.77,-3128.22 h60
  text "LAYER NAME =" at -696.27,-3311.55 h60
  text "TID #:" at 1787.73,-3317.22 h60
  text ".PRJ_Number" at 2153.23,-3317.22 h60
  text ".plot_File_Name" at -704.27,-3510.55 h60
  text "GENERATED    :" at 1784.73,-3530.88 h60
  text ".Print_Date" at 2654.23,-3530.88 h60
  text ".Print_Time" at 3383.23,-3530.88 h60
  text "TEXAS INSTRUMENTS" at 4647.73,-3530.88 h60
M12 Stackup:
  lines w6: 10894.73,4993.45 13444.73,4993.45 ; 10894.73,5097.85 13444.73,5097.85 ; 10834.73,4508.45 ccw(c10868.73,4508.45) 10868.73,4474.45 13470.73,4474.45 ccw(c13470.73,4508.45) 13504.73,4508.45 13504.73,5214.45 ccw(c13470.73,5214.45) 13470.73,5248.45 10868.73,5248.45 ccw(c10868.73,5214.45) 10834.73,5214.45 10834.73,4508.45
  text "Layer Stack Up Detail for: TIDA-00366-E2" at 10894.73,5130.55 h57
  text "Layer" at 10894.73,5058.85 h24
  text "Gerber" at 11790.55,5058.85 h24
  text "Copper" at 12354.07,5058.85 h24
  text "Dielectric" at 12956.77,5058.85 h24
  text "Name" at 10894.73,5010.85 h24
  text "Document" at 11790.55,5010.85 h24
  text "Thickness" at 12354.07,5010.85 h24
  text "Material" at 12956.77,5010.85 h24
  text "Top Solder Mask" at 10909.73,4919.45 h34
  text "(.GTS)" at 11790.55,4917.89 h34
  text "Solder Resist" at 12956.77,4917.89 h34
  text "Top Layer" at 10904.73,4824.45 h34
  text "(.GTL)" at 11790.55,4821.14 h34
  text "1.4mil" at 12354.07,4821.14 h34
  text "FR4-High Tg" at 12985.73,4820.45 h34
  text "FR4-High Tg" at 12990.73,4765.45 h34
  text "1.4mil" at 12354.07,4756.14 h34
  text "GND" at 10903.73,4752.45 h34
  text "(.G1)" at 11789.55,4744.14 h34
  text "FR4-High Tg" at 12990.73,4690.45 h34
  text "1.4mil" at 12354.07,4686.14 h34
  text "(.G2)" at 11789.55,4674.14 h34
  text "PWR" at 10903.73,4672.45 h34
  text "FR4-High Tg" at 12990.73,4595.45 h34
  text "Bottom Layer" at 10899.73,4594.45 h34
  text "(.GBL)" at 11798.73,4590.45 h34
  text "1.4mil" at 12358.73,4584.45 h34
  text "Solder Resist" at 12950.73,4517.45 h34
  text "(.GBS)" at 11795.73,4510.45 h34
  text "Bottom Solder Mask" at 10904.73,4509.45 h34
M13 Component Bodies Top:
  text ".Layer_Name" at 111.73,-3325.04 h60
M14 Component Bodies Bottom:
  text ".Layer_Name" at 111.73,-3325.04 h60
M15 Courtyards Top:
  text ".Layer_Name" at 111.73,-3325.04 h60
M16 Courtyards Bottom:
  text ".Layer_Name" at 111.73,-3325.04 h60
Drill Drawing:
  circle w10: c6842.62,4398.83 r20
  circle w10: c6842.62,4398.83 r33.33
  lines w10: 6809.29,4532.17 6825.96,4532.17 6825.96,4515.5 6859.29,4515.5 6859.29,4532.17 6875.96,4532.17 6875.96,4565.5 6859.29,4565.5 6859.29,4582.17 6825.96,4582.17 6825.96,4565.5 6809.29,4565.5 6809.29,4532.17 ; 6809.29,4682.17 6825.96,4682.17 6842.62,4665.5 6859.29,4682.17 6875.96,4682.17 6859.29,4698.83 6875.96,4715.5 6859.29,4715.5 6842.62,4732.17 6825.96,4715.5 6809.29,4715.5 6825.96,4698.83 6809.29,4682.17 ; 6809.29,4815.5 6875.96,4815.5 6875.96,4882.17 6809.29,4882.17 6809.29,4815.5 ; 6809.29,5115.5 6842.62,5132.17 6875.96,5115.5 6859.29,5148.83 6875.96,5182.17 6842.62,5165.5 6809.29,5182.17 6825.96,5148.83 6809.29,5115.5 ; 6809.29,5265.5 6809.29,5282.17 6825.96,5298.83 6809.29,5315.5 6809.29,5332.17 6825.96,5332.17 6842.62,5315.5 6859.29,5332.17 6875.96,5332.17 6875.96,5315.5 6859.29,5298.83 6875.96,5282.17 6875.96,5265.5 6859.29,5265.5 6842.62,5282.17 6825.96,5265.5 6809.29,5265.5 ; 6809.29,5415.5 6875.96,5415.5 6875.96,5482.17 6809.29,5482.17 6809.29,5415.5 ; 6822.62,4538.83 6832.62,4538.83 6832.62,4528.83 6852.62,4528.83 6852.62,4538.83 6862.62,4538.83 6862.62,4558.83 6852.62,4558.83 6852.62,4568.83 6832.62,4568.83 6832.62,4558.83 6822.62,4558.83 6822.62,4538.83 ; 6822.62,4688.83 6832.62,4688.83 6842.62,4678.83 6852.62,4688.83 6862.62,4688.83 6852.62,4698.83 6862.62,4708.83 6852.62,4708.83 6842.62,4718.83 6832.62,4708.83 6822.62,4708.83 6832.62,4698.83 6822.62,4688.83 ; 6822.62,4828.83 6862.62,4828.83 6862.62,4868.83 6822.62,4868.83 6822.62,4828.83 ; 6822.62,5128.83 6842.62,5138.83 6862.62,5128.83 6852.62,5148.83 6862.62,5168.83 6842.62,5158.83 6822.62,5168.83 6832.62,5148.83 6822.62,5128.83 ; 6822.62,5278.83 6822.62,5288.83 6832.62,5298.83 6822.62,5308.83 6822.62,5318.83 6832.62,5318.83 6842.62,5308.83 6852.62,5318.83 6862.62,5318.83 6862.62,5308.83 6852.62,5298.83 6862.62,5288.83 6862.62,5278.83 6852.62,5278.83 6842.62,5288.83 6832.62,5278.83 6822.62,5278.83
  lines w15: 6749.5,4320.5 10344.56,4320.5 ; 6749.5,5970.5 10344.56,5970.5 ; 7300.38,4170.5 7300.38,6120.5 ; 7900.22,4170.5 7900.22,6120.5 ; 9059.88,4170.5 9059.88,6120.5 ; 9565.75,4170.5 9565.75,6120.5 ; 6749.5,4170.5 10344.56,4170.5 10344.56,6120.5 6749.5,6120.5 6749.5,4170.5
  text ".legend" at 7345,6234 h60
  text "Symbol" at 6839.5,6015.5 h72
  text "Count" at 7345.38,6015.5 h72
  text "Hole Size" at 7945.22,6015.5 h72
  text "Plated" at 9104.88,6015.5 h72
  text "Hole Type" at 9610.75,6015.5 h72
  text "271" at 7345.38,5865.5 h60
  text "16.00mil (0.406mm)" at 7945.22,5865.5 h60
  text "PTH" at 9104.88,5865.5 h60
  text "Round" at 9610.75,5865.5 h60
  text "C" at 6810.41,5855.51 h66.67
  text "6" at 7345.38,5715.5 h60
  text "33.47mil (0.850mm)" at 7945.22,5715.5 h60
  text "PTH" at 9104.88,5715.5 h60
  text "Round" at 9610.75,5715.5 h60
  text "B" at 6810.41,5705.51 h66.67
  text "50" at 7345.38,5565.5 h60
  text "40.00mil (1.016mm)" at 7945.22,5565.5 h60
  text "PTH" at 9104.88,5565.5 h60
  text "Round" at 9610.75,5565.5 h60
  text "A" at 6810.41,5555.51 h66.67
  text "4" at 7345.38,5415.5 h60
  text "41.34mil (1.050mm)" at 7945.22,5415.5 h60
  text "PTH" at 9104.88,5415.5 h60
  text "Round" at 9610.75,5415.5 h60
  text "4" at 7345.38,5265.5 h60
  text "43.31mil (1.100mm)" at 7945.22,5265.5 h60
  text "PTH" at 9104.88,5265.5 h60
  text "Round" at 9610.75,5265.5 h60
  text "60" at 7345.38,5115.5 h60
  text "58.07mil (1.475mm)" at 7945.22,5115.5 h60
  text "PTH" at 9104.88,5115.5 h60
  text "Round" at 9610.75,5115.5 h60
  text "34" at 7345.38,4965.5 h60
  text "66.93mil (1.700mm)" at 7945.22,4965.5 h60
  text "PTH" at 9104.88,4965.5 h60
  text "Round" at 9610.75,4965.5 h60
  text "E" at 6810.41,4955.51 h66.67
  text "4" at 7345.38,4815.5 h60
  text "98.43mil (2.500mm)" at 7945.22,4815.5 h60
  text "NPTH" at 9104.88,4815.5 h60
  text "Round" at 9610.75,4815.5 h60
  text "4" at 7345.38,4665.5 h60
  text "128.00mil (3.251mm)" at 7945.22,4665.5 h60
  text "NPTH" at 9104.88,4665.5 h60
  text "Round" at 9610.75,4665.5 h60
  text "5" at 7345.38,4515.5 h60
  text "208.66mil (5.300mm)" at 7945.22,4515.5 h60
  text "NPTH" at 9104.88,4515.5 h60
  text "Round" at 9610.75,4515.5 h60
  text "2" at 7345.38,4365.5 h60
  text "236.22mil (6.000mm)" at 7945.22,4365.5 h60
  text "NPTH" at 9104.88,4365.5 h60
  text "Round" at 9610.75,4365.5 h60
  text "444 Total" at 7345.38,4215.5 h60
  text "Drill Table" at 7499,4025 h60
  text "FOR 16MIL DRILL +0/-16MIL" at 7499,3905 h60
  text "FOR PTH DRILL +/-3MIL" at 7494.73,3813.45 h60
  text "FOR NPTH DRILL +/-2MIL" at 7499,3730 h60
  text "This not an impedance controlled board" at 7385,3400 h60
  text "All Vias are non tented" at 7384,3278 h60
  text ".layer_Name" at 216.73,-3308.55 h60

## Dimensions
0,0 to 0,4960.63 on M2 Board Dimensions
0,4960.63 to 1934.73,4960.63 on M2 Board Dimensions
1934.73,0 to 1934.73,-590.55 on M2 Board Dimensions
0,0 to 6299.21,-590.55 on M2 Board Dimensions
6299.21,5551.18 to 6299.21,-590.55 on M2 Board Dimensions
